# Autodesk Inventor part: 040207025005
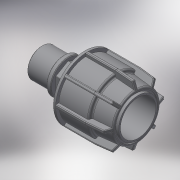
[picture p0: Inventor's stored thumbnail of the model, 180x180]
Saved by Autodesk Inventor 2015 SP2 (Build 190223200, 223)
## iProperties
Created: 2017-08
Part Number: 040207025005
Material: Generic
Description: PLASSON IRRIFIT ADAPTOR 25-1/2"M
Document SubType Name: Modeling
Designer: KIM
Density: 1 g/cm^3
Appearance: Default
Author: KIM
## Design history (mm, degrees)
derived "040207.ipt"
feature "Solid1::040207.ipt"
tag "TaggingFeature1"
body "Solid1"
other parameters: "d5" = 36.4, "d6" = 15.84, "d10" = 45, "d22" = 20.955, "d24" = 1.656, "d25" = 40.5, "d26" = 36, "d31" = 1, "d49" = 2.25, "d50" = 0, "d58" = 0.5, "d61" = 360 deg, "d77" = 25, "d78" = 5 deg, "d80" = 27.5, "d81" = 36, "d82" = 2.16, "d84" = 5 deg, "d85" = 70 deg, "d86" = 42.75, "d87" = 0.36, "d88" = 0, "d89" = 38.25, "d90" = 3.6, "d91" = 0, "d99" = 20.955, "d100" = 16, "d101" = 3.2, "d102" = 72, "d103" = 25.146, "d104" = 0.4191, "d108" = 0, "d109" = 0.20955, "d112" = 16.764, "d113" = 29.12, "d_" = 25, "E_" = 45, "H_" = 72, "l_nut" = 36.4, "l_" = 16, "R_" = 20.955
